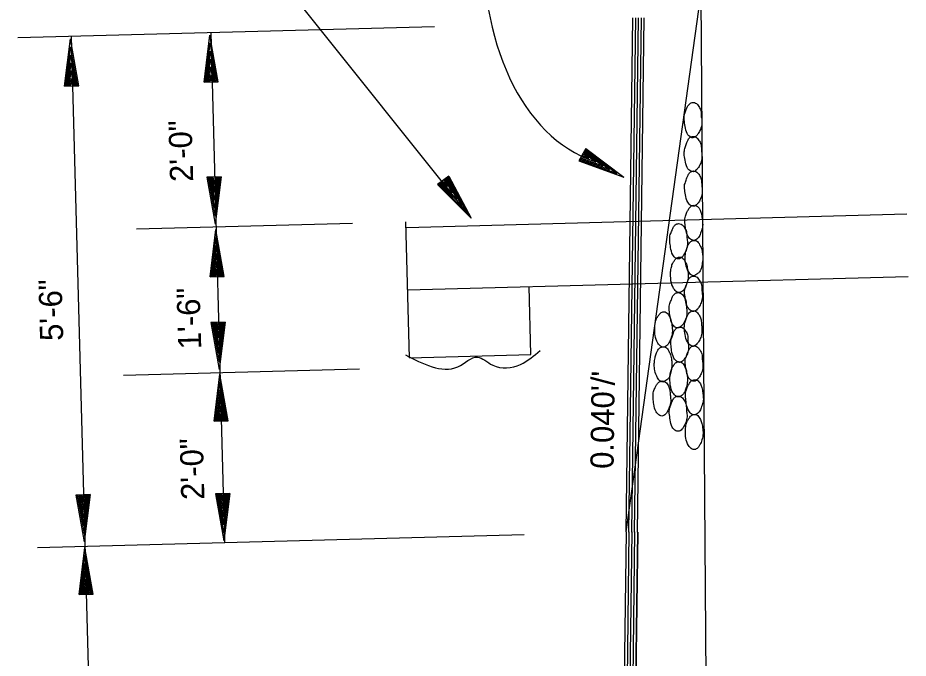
# Model space of a CAD drawing. Extents: x 1929624 to 1935547, y 596315 to 605721.
# Drawn here: x 1931754.9 to 1931985.3, y 600586 to 600751.8 of the extents above; entities that cross this region are included whole.
import ezdxf

# ---------------------------------------------------------------- set-up
doc = ezdxf.new("R2010")
doc.units = 0
doc.layers.add('Default', color=7, linetype='Continuous')

msp = doc.modelspace()

# ---------------------------------------------------------------- linework, layer by layer
at = {"layer": 'Default'}
for p, q in [((1931912.31, 600618.68), (1931945.12, 600854.29)), ((1931934.09, 600420.4), (1931931.39, 600809)), ((1931872.05, 600700.18), (1931818.5, 600767.22)), ((1931912.31, 600618.68), (1931914.06, 600751.77)), ((1931913.04, 600618.66), (1931914.79, 600751.75)), ((1931913.77, 600618.66), (1931915.52, 600751.74)), ((1931914.5, 600618.64), (1931916.25, 600751.73)), ((1931915.23, 600618.64), (1931916.98, 600751.73)), ((1931862.75, 600749.44), (1931754.9, 600746.55)), ((1931766.98, 600734.09), (1931768.5, 600746.31)), ((1931770.65, 600734.19), (1931768.5, 600746.31)), ((1931777.56, 600420.59), (1931768.8, 600746.92)), ((1931803.1, 600735.06), (1931804.62, 600747.28)), ((1931806.77, 600735.16), (1931804.62, 600747.28)), ((1931808.44, 600615.89), (1931804.9, 600747.89)), ((1931767.3, 600734.1), (1931768.55, 600744.27)), ((1931770.33, 600734.18), (1931768.55, 600744.27)), ((1931803.42, 600735.07), (1931804.68, 600745.24)), ((1931806.45, 600735.15), (1931804.68, 600745.24)), ((1931767.61, 600734.1), (1931768.61, 600742.18)), ((1931770.02, 600734.17), (1931768.61, 600742.18)), ((1931803.73, 600735.07), (1931804.73, 600743.15)), ((1931806.14, 600735.14), (1931804.73, 600743.15)), ((1931767.9, 600734.11), (1931768.67, 600740.14)), ((1931769.73, 600734.16), (1931768.67, 600740.14)), ((1931804.02, 600735.08), (1931804.79, 600741.11)), ((1931805.85, 600735.13), (1931804.79, 600741.11)), ((1931768.22, 600734.12), (1931768.72, 600738.1)), ((1931769.41, 600734.15), (1931768.72, 600738.1)), ((1931804.34, 600735.09), (1931804.84, 600739.07)), ((1931805.53, 600735.12), (1931804.84, 600739.07)), ((1931768.53, 600734.13), (1931768.77, 600736.06)), ((1931769.09, 600734.14), (1931768.77, 600736.06)), ((1931803.1, 600735.06), (1931806.77, 600735.16)), ((1931804.66, 600735.1), (1931804.9, 600737.03)), ((1931805.21, 600735.11), (1931804.9, 600737.03)), ((1931766.98, 600734.09), (1931770.65, 600734.19)), ((1931901.84, 600717.94), (1931900.08, 600714.74)), ((1931901.1, 600716.59), (1931902.66, 600715.44)), ((1931901.26, 600716.86), (1931904.44, 600714.44)), ((1931901.4, 600717.13), (1931906.26, 600713.44)), ((1931901.56, 600717.38), (1931908.02, 600712.5)), ((1931901.68, 600717.7), (1931909.87, 600711.5)), ((1931901.84, 600717.94), (1931911.67, 600710.53)), ((1931900.08, 600714.74), (1931911.67, 600710.53)), ((1931900.27, 600714.99), (1931909.87, 600711.5)), ((1931900.41, 600715.28), (1931908.02, 600712.5)), ((1931900.54, 600715.53), (1931906.26, 600713.44)), ((1931900.68, 600715.82), (1931904.44, 600714.44)), ((1931900.84, 600716.12), (1931902.66, 600715.44)), ((1931807.5, 600710.57), (1931803.83, 600710.48)), ((1931803.83, 600710.48), (1931805.98, 600698.36)), ((1931804.15, 600710.48), (1931805.93, 600700.4)), ((1931804.47, 600710.49), (1931805.87, 600702.48)), ((1931804.76, 600710.5), (1931805.82, 600704.53)), ((1931805.07, 600710.51), (1931805.76, 600706.57)), ((1931805.39, 600710.52), (1931805.71, 600708.61)), ((1931805.95, 600710.53), (1931805.71, 600708.61)), ((1931806.26, 600710.54), (1931805.76, 600706.57)), ((1931806.58, 600710.55), (1931805.82, 600704.53)), ((1931806.87, 600710.56), (1931805.87, 600702.48)), ((1931807.19, 600710.57), (1931805.93, 600700.4)), ((1931807.5, 600710.57), (1931805.98, 600698.36)), ((1931866.42, 600710.73), (1931863.51, 600708.59)), ((1931864.75, 600709.49), (1931866.1, 600708.12)), ((1931865.15, 600709.85), (1931866.1, 600708.12)), ((1931865.42, 600709.97), (1931867.31, 600706.47)), ((1931865.68, 600710.18), (1931868.52, 600704.85)), ((1931865.94, 600710.35), (1931869.71, 600703.23)), ((1931866.2, 600710.58), (1931871.01, 600701.49)), ((1931866.42, 600710.73), (1931872.2, 600699.87)), ((1931863.51, 600708.59), (1931872.2, 600699.87)), ((1931863.74, 600708.79), (1931871.01, 600701.49)), ((1931864.03, 600708.99), (1931869.71, 600703.23)), ((1931864.28, 600709.12), (1931868.52, 600704.85)), ((1931864.48, 600709.31), (1931867.31, 600706.47)), ((1931855.47, 600697.52), (1931984.97, 600701)), ((1931841.49, 600698.55), (1931785.65, 600697.06)), ((1931856.23, 600663.73), (1931855.29, 600698.93)), ((1931804.65, 600684.71), (1931806.17, 600696.93)), ((1931808.32, 600684.8), (1931806.17, 600696.93)), ((1931804.96, 600684.71), (1931806.22, 600694.89)), ((1931808, 600684.8), (1931806.22, 600694.89)), ((1931805.28, 600684.72), (1931806.28, 600692.8)), ((1931807.68, 600684.79), (1931806.28, 600692.8)), ((1931805.57, 600684.73), (1931806.33, 600690.76)), ((1931805.89, 600684.74), (1931806.39, 600688.72)), ((1931807.39, 600684.78), (1931806.33, 600690.76)), ((1931807.08, 600684.77), (1931806.39, 600688.72)), ((1931806.2, 600684.75), (1931806.44, 600686.68)), ((1931806.76, 600684.76), (1931806.44, 600686.68)), ((1931804.65, 600684.71), (1931808.32, 600684.8)), ((1931855.76, 600681.34), (1931985.28, 600684.82)), ((1931887.67, 600664.57), (1931887.19, 600682.18)), ((1931808.54, 600672.97), (1931804.87, 600672.87)), ((1931804.87, 600672.87), (1931807.02, 600660.75)), ((1931805.18, 600672.88), (1931806.96, 600662.79)), ((1931805.5, 600672.89), (1931806.91, 600664.88)), ((1931805.79, 600672.9), (1931806.85, 600666.92)), ((1931806.11, 600672.91), (1931806.8, 600668.96)), ((1931806.42, 600672.92), (1931806.74, 600671)), ((1931806.98, 600672.93), (1931806.74, 600671)), ((1931807.3, 600672.94), (1931806.8, 600668.96)), ((1931807.61, 600672.95), (1931806.85, 600666.92)), ((1931807.9, 600672.96), (1931806.91, 600664.88)), ((1931808.22, 600672.96), (1931806.96, 600662.79)), ((1931808.54, 600672.97), (1931807.02, 600660.75)), ((1931856.23, 600663.73), (1931887.67, 600664.57)), ((1931843.3, 600660.85), (1931782.21, 600659.21)), ((1931805.68, 600647.32), (1931807.19, 600659.54)), ((1931809.34, 600647.42), (1931807.19, 600659.54)), ((1931805.99, 600647.33), (1931807.25, 600657.5)), ((1931809.03, 600647.41), (1931807.25, 600657.5)), ((1931806.31, 600647.34), (1931807.31, 600655.41)), ((1931808.71, 600647.4), (1931807.31, 600655.41)), ((1931806.6, 600647.35), (1931807.36, 600653.37)), ((1931808.42, 600647.4), (1931807.36, 600653.37)), ((1931806.91, 600647.36), (1931807.42, 600651.33)), ((1931808.1, 600647.39), (1931807.42, 600651.33)), ((1931805.68, 600647.32), (1931809.34, 600647.42)), ((1931807.23, 600647.36), (1931807.47, 600649.29)), ((1931807.79, 600647.38), (1931807.47, 600649.29)), ((1931773.61, 600628.33), (1931769.94, 600628.23)), ((1931769.94, 600628.23), (1931772.09, 600616.11)), ((1931770.26, 600628.24), (1931772.04, 600618.15)), ((1931770.58, 600628.25), (1931771.98, 600620.24)), ((1931770.87, 600628.25), (1931771.93, 600622.28)), ((1931771.18, 600628.26), (1931771.87, 600624.32)), ((1931771.5, 600628.27), (1931771.82, 600626.36)), ((1931772.06, 600628.29), (1931771.82, 600626.36)), ((1931772.37, 600628.29), (1931771.87, 600624.32)), ((1931772.69, 600628.3), (1931771.93, 600622.28)), ((1931772.98, 600628.31), (1931771.98, 600620.24)), ((1931773.3, 600628.32), (1931772.04, 600618.15)), ((1931773.61, 600628.33), (1931772.09, 600616.11)), ((1931809.73, 600628.64), (1931806.06, 600628.54)), ((1931806.06, 600628.54), (1931808.21, 600616.42)), ((1931806.37, 600628.55), (1931808.15, 600618.46)), ((1931806.69, 600628.56), (1931808.1, 600620.55)), ((1931806.98, 600628.57), (1931808.04, 600622.59)), ((1931807.3, 600628.58), (1931807.99, 600624.63)), ((1931807.61, 600628.58), (1931807.93, 600626.67)), ((1931808.17, 600628.6), (1931807.93, 600626.67)), ((1931808.49, 600628.61), (1931807.99, 600624.63)), ((1931808.8, 600628.62), (1931808.04, 600622.59)), ((1931809.09, 600628.62), (1931808.1, 600620.55)), ((1931809.41, 600628.63), (1931808.15, 600618.46)), ((1931809.73, 600628.64), (1931808.21, 600616.42)), ((1931885.93, 600617.97), (1931760, 600614.59)), ((1931912.31, 600618.68), (1931910.39, 600472.78)), ((1931913.04, 600618.7), (1931911.12, 600472.8)), ((1931913.77, 600618.67), (1931911.85, 600472.77)), ((1931914.5, 600618.69), (1931912.58, 600472.79)), ((1931915.23, 600618.66), (1931913.31, 600472.76)), ((1931915.32, 600618.66), (1931913.4, 600472.86)), ((1931770.73, 600602.46), (1931772.25, 600614.68)), ((1931774.4, 600602.56), (1931772.25, 600614.68)), ((1931771.05, 600602.47), (1931772.31, 600612.64)), ((1931771.36, 600602.48), (1931772.36, 600610.55)), ((1931774.08, 600602.55), (1931772.31, 600612.64)), ((1931773.77, 600602.54), (1931772.36, 600610.55)), ((1931771.66, 600602.48), (1931772.42, 600608.51)), ((1931773.48, 600602.53), (1931772.42, 600608.51)), ((1931771.97, 600602.49), (1931772.47, 600606.47)), ((1931773.16, 600602.52), (1931772.47, 600606.47)), ((1931772.29, 600602.5), (1931772.53, 600604.43)), ((1931772.85, 600602.52), (1931772.53, 600604.43)), ((1931770.73, 600602.46), (1931774.4, 600602.56))]:
    msp.add_line(p, q, dxfattribs=at)
msp.add_ellipse((1931915.32, 600773.75), major_axis=(-5.72, -60.23), ratio=0.655798, start_param=4.712389, end_param=6.093533, dxfattribs=at)
for points in [[(1931927.31, 600725.35), (1931927.55, 600723.65), (1931928.09, 600721.77), (1931929.04, 600720.82), (1931929.58, 600720.69), (1931930.53, 600721.25), (1931930.96, 600721.8), (1931931.51, 600722.88), (1931931.91, 600724.45), (1931931.89, 600725.23), (1931931.71, 600726.44), (1931931.62, 600727.8), (1931931.11, 600728.8), (1931930.26, 600729.7), (1931929.62, 600729.83), (1931928.76, 600729.52), (1931928.19, 600728.77), (1931927.87, 600728.03), (1931927.51, 600727), (1931927.33, 600726.32), (1931927.31, 600725.35)], [(1931927.3, 600716.57), (1931927.54, 600714.92), (1931928.12, 600712.99), (1931929.02, 600712.05), (1931929.61, 600711.92), (1931930.57, 600712.48), (1931930.99, 600713.02), (1931931.59, 600714.16), (1931931.89, 600715.67), (1931931.87, 600716.45), (1931931.79, 600717.66), (1931931.61, 600719.02), (1931931.14, 600720.03), (1931930.24, 600720.93), (1931929.66, 600721.06), (1931928.79, 600720.74), (1931928.23, 600720), (1931927.91, 600719.26), (1931927.59, 600718.23), (1931927.42, 600717.59), (1931927.3, 600716.57)], [(1931927.42, 600707.57), (1931927.65, 600705.97), (1931928.24, 600704.04), (1931929.14, 600703.1), (1931929.73, 600702.97), (1931930.69, 600703.53), (1931931.11, 600704.07), (1931931.66, 600705.16), (1931932.01, 600706.67), (1931931.99, 600707.5), (1931931.86, 600708.71), (1931931.73, 600710.02), (1931931.26, 600711.03), (1931930.36, 600711.98), (1931929.77, 600712.11), (1931928.91, 600711.79), (1931928.34, 600711.05), (1931928.02, 600710.31), (1931927.66, 600709.23), (1931927.44, 600708.59), (1931927.42, 600707.57)], [(1931927.51, 600698.7), (1931927.7, 600697.1), (1931928.33, 600695.17), (1931929.23, 600694.27), (1931929.82, 600694.14), (1931930.78, 600694.66), (1931931.2, 600695.15), (1931931.66, 600696.28), (1931932.1, 600697.8), (1931932.08, 600698.63), (1931931.95, 600699.84), (1931931.72, 600701.2), (1931931.35, 600702.16), (1931930.45, 600703.11), (1931929.87, 600703.24), (1931929, 600702.92), (1931928.44, 600702.18), (1931928.02, 600701.44), (1931927.66, 600700.41), (1931927.53, 600699.72), (1931927.51, 600698.7)], [(1931923.58, 600693.91), (1931923.82, 600692.31), (1931924.35, 600690.43), (1931925.3, 600689.48), (1931925.84, 600689.35), (1931926.85, 600689.92), (1931927.27, 600690.46), (1931927.82, 600691.55), (1931928.17, 600693.11), (1931928.15, 600693.89), (1931928.02, 600695.1), (1931927.89, 600696.41), (1931927.37, 600697.47), (1931926.52, 600698.37), (1931925.89, 600698.49), (1931925.02, 600698.18), (1931924.46, 600697.44), (1931924.18, 600696.7), (1931923.73, 600695.67), (1931923.6, 600694.93), (1931923.58, 600693.91)], [(1931927.57, 600689.56), (1931927.71, 600687.96), (1931928.44, 600686.08), (1931929.24, 600685.13), (1931929.78, 600685), (1931930.79, 600685.56), (1931931.31, 600686.02), (1931931.76, 600687.2), (1931932.07, 600688.66), (1931932.14, 600689.49), (1931932.06, 600690.7), (1931931.78, 600692.06), (1931931.32, 600693.02), (1931930.51, 600694.02), (1931929.88, 600694.15), (1931929.01, 600693.83), (1931928.4, 600693.08), (1931928.08, 600692.35), (1931927.77, 600691.27), (1931927.64, 600690.58), (1931927.57, 600689.56)], [(1931923.81, 600685.26), (1931923.9, 600683.65), (1931924.59, 600681.73), (1931925.53, 600680.78), (1931926.07, 600680.65), (1931927.08, 600681.21), (1931927.5, 600681.76), (1931927.96, 600682.84), (1931928.31, 600684.4), (1931928.38, 600685.23), (1931928.25, 600686.4), (1931927.97, 600687.7), (1931927.56, 600688.71), (1931926.76, 600689.66), (1931926.12, 600689.79), (1931925.25, 600689.48), (1931924.69, 600688.73), (1931924.27, 600688.04), (1931923.96, 600686.96), (1931923.83, 600686.28), (1931923.81, 600685.26)], [(1931927.44, 600680.39), (1931927.68, 600678.7), (1931928.22, 600676.87), (1931929.17, 600675.87), (1931929.71, 600675.74), (1931930.71, 600676.3), (1931931.13, 600676.85), (1931931.69, 600677.98), (1931932.04, 600679.5), (1931932.01, 600680.27), (1931931.88, 600681.49), (1931931.75, 600682.89), (1931931.24, 600683.85), (1931930.39, 600684.75), (1931929.75, 600684.88), (1931928.89, 600684.57), (1931928.32, 600683.82), (1931928.05, 600683.13), (1931927.69, 600682.05), (1931927.46, 600681.42), (1931927.44, 600680.39)], [(1931923.43, 600676.06), (1931923.66, 600674.46), (1931924.2, 600672.58), (1931925.15, 600671.63), (1931925.69, 600671.5), (1931926.69, 600672.06), (1931927.12, 600672.61), (1931927.67, 600673.69), (1931928.02, 600675.26), (1931928, 600676.03), (1931927.87, 600677.25), (1931927.73, 600678.55), (1931927.22, 600679.61), (1931926.37, 600680.51), (1931925.73, 600680.64), (1931924.87, 600680.33), (1931924.3, 600679.58), (1931924.03, 600678.84), (1931923.57, 600677.81), (1931923.45, 600677.08), (1931923.43, 600676.06)], [(1931919.7, 600671.1), (1931919.79, 600669.5), (1931920.53, 600667.58), (1931921.43, 600666.63), (1931922.01, 600666.5), (1931922.97, 600667.06), (1931923.39, 600667.6), (1931923.85, 600668.69), (1931924.25, 600670.25), (1931924.27, 600671.08), (1931924.14, 600672.24), (1931923.87, 600673.55), (1931923.45, 600674.56), (1931922.65, 600675.51), (1931922.06, 600675.64), (1931921.19, 600675.32), (1931920.63, 600674.58), (1931920.16, 600673.89), (1931919.85, 600672.81), (1931919.72, 600672.12), (1931919.7, 600671.1)], [(1931927.32, 600671.43), (1931927.56, 600669.78), (1931928.14, 600667.85), (1931929.04, 600666.91), (1931929.63, 600666.78), (1931930.59, 600667.34), (1931931.01, 600667.88), (1931931.61, 600669.02), (1931931.91, 600670.53), (1931931.89, 600671.31), (1931931.81, 600672.52), (1931931.63, 600673.88), (1931931.16, 600674.89), (1931930.26, 600675.79), (1931929.68, 600675.92), (1931928.81, 600675.6), (1931928.25, 600674.86), (1931927.93, 600674.12), (1931927.61, 600673.09), (1931927.44, 600672.45), (1931927.32, 600671.43)], [(1931923.89, 600667.22), (1931924.08, 600665.62), (1931924.66, 600663.69), (1931925.62, 600662.7), (1931926.15, 600662.57), (1931927.11, 600663.13), (1931927.53, 600663.67), (1931928.14, 600664.81), (1931928.43, 600666.32), (1931928.41, 600667.15), (1931928.28, 600668.31), (1931928.2, 600669.72), (1931927.69, 600670.68), (1931926.84, 600671.58), (1931926.2, 600671.71), (1931925.33, 600671.39), (1931924.77, 600670.7), (1931924.45, 600669.96), (1931924.14, 600668.93), (1931923.86, 600668.24), (1931923.89, 600667.22)], [(1931855.19, 600664.55), (1931862.11, 600661.43), (1931868.77, 600661.44), (1931873.83, 600663.96), (1931877.77, 600661.85), (1931884.94, 600662.04), (1931890.02, 600665.68)], [(1931919.58, 600662.03), (1931919.72, 600660.43), (1931920.45, 600658.56), (1931921.25, 600657.6), (1931921.79, 600657.47), (1931922.8, 600658.04), (1931923.32, 600658.49), (1931923.78, 600659.67), (1931924.08, 600661.13), (1931924.15, 600661.96), (1931924.07, 600663.17), (1931923.79, 600664.53), (1931923.33, 600665.49), (1931922.52, 600666.49), (1931921.89, 600666.62), (1931921.02, 600666.3), (1931920.41, 600665.56), (1931920.09, 600664.82), (1931919.78, 600663.74), (1931919.65, 600663.06), (1931919.58, 600662.03)], [(1931927.57, 600662.29), (1931927.81, 600660.69), (1931928.39, 600658.76), (1931929.3, 600657.81), (1931929.88, 600657.68), (1931930.84, 600658.24), (1931931.26, 600658.79), (1931931.82, 600659.87), (1931932.17, 600661.39), (1931932.14, 600662.22), (1931932.01, 600663.43), (1931931.88, 600664.74), (1931931.42, 600665.75), (1931930.52, 600666.69), (1931929.93, 600666.82), (1931929.06, 600666.51), (1931928.5, 600665.76), (1931928.18, 600665.03), (1931927.82, 600663.95), (1931927.59, 600663.31), (1931927.57, 600662.29)], [(1931923.64, 600658.23), (1931923.73, 600656.63), (1931924.41, 600654.7), (1931925.36, 600653.75), (1931925.9, 600653.62), (1931926.91, 600654.18), (1931927.33, 600654.73), (1931927.79, 600655.81), (1931928.13, 600657.38), (1931928.21, 600658.2), (1931928.08, 600659.37), (1931927.8, 600660.67), (1931927.38, 600661.68), (1931926.58, 600662.63), (1931925.95, 600662.76), (1931925.08, 600662.45), (1931924.52, 600661.7), (1931924.1, 600661.01), (1931923.79, 600659.93), (1931923.66, 600659.25), (1931923.64, 600658.23)], [(1931919.3, 600653.31), (1931919.44, 600651.71), (1931920.07, 600649.79), (1931921.02, 600648.79), (1931921.56, 600648.66), (1931922.52, 600649.17), (1931922.94, 600649.77), (1931923.44, 600650.9), (1931923.84, 600652.46), (1931923.82, 600653.29), (1931923.69, 600654.45), (1931923.51, 600655.76), (1931923.09, 600656.77), (1931922.24, 600657.62), (1931921.61, 600657.75), (1931920.74, 600657.44), (1931920.17, 600656.79), (1931919.8, 600656.1), (1931919.4, 600655.02), (1931919.27, 600654.33), (1931919.3, 600653.31)], [(1931927.68, 600653.55), (1931927.86, 600651.95), (1931928.5, 600650.02), (1931929.4, 600649.12), (1931929.99, 600648.99), (1931930.94, 600649.5), (1931931.37, 600650), (1931931.82, 600651.13), (1931932.27, 600652.65), (1931932.25, 600653.48), (1931932.12, 600654.69), (1931931.89, 600656.04), (1931931.52, 600657.01), (1931930.62, 600657.95), (1931930.03, 600658.08), (1931929.17, 600657.77), (1931928.6, 600657.02), (1931928.19, 600656.28), (1931927.82, 600655.25), (1931927.7, 600654.57), (1931927.68, 600653.55)], [(1931923.46, 600649.4), (1931923.7, 600647.7), (1931924.24, 600645.82), (1931925.19, 600644.88), (1931925.72, 600644.74), (1931926.73, 600645.26), (1931927.15, 600645.85), (1931927.71, 600646.94), (1931928.05, 600648.5), (1931928.03, 600649.28), (1931927.9, 600650.49), (1931927.77, 600651.85), (1931927.26, 600652.86), (1931926.41, 600653.71), (1931925.77, 600653.84), (1931924.91, 600653.52), (1931924.34, 600652.78), (1931924.07, 600652.09), (1931923.66, 600651.01), (1931923.48, 600650.37), (1931923.46, 600649.4)], [(1931927.63, 600644.55), (1931927.73, 600642.95), (1931928.46, 600641.03), (1931929.36, 600640.13), (1931929.94, 600640), (1931930.9, 600640.51), (1931931.32, 600641.1), (1931931.78, 600642.14), (1931932.18, 600643.75), (1931932.2, 600644.53), (1931932.07, 600645.74), (1931931.8, 600647.05), (1931931.38, 600648.06), (1931930.58, 600648.96), (1931929.99, 600649.09), (1931929.12, 600648.77), (1931928.56, 600648.03), (1931928.09, 600647.34), (1931927.78, 600646.26), (1931927.65, 600645.57), (1931927.63, 600644.55)]]:
    msp.add_spline(points, degree=3, dxfattribs=at)

# ---------------------------------------------------------------- texts
for s, rotation, p in [('2\'-0"', 91.5377, (1931800.29, 600709.36)), ('5\'-6"', 91.5377, (1931766.66, 600668.2)), ('1\'-6"', 91.5377, (1931802.38, 600666.03)), ("0.040'/'", 89.2471, (1931909.04, 600634.98)), ('2\'-0"', 91.5377, (1931803.2, 600627.06))]:
    msp.add_text(s, height=6, rotation=rotation, dxfattribs=at).set_placement(p)

doc.saveas('drawing.dxf')
